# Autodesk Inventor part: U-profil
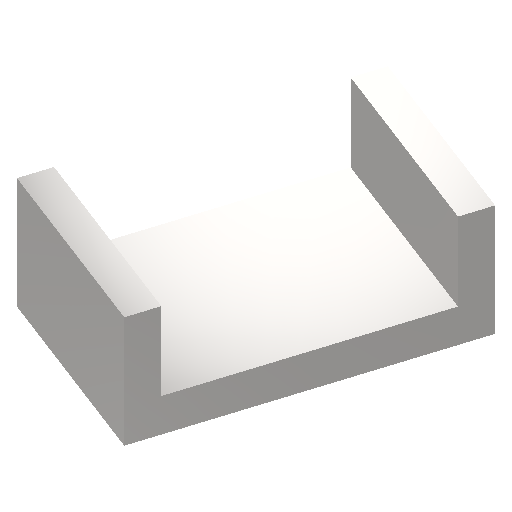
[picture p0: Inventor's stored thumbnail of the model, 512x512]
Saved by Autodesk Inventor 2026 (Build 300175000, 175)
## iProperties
Created: 2004-09
Part Number: U-profil
Document SubType Name: Modeling
Designer: Lars Bertram Pedersen
Manufacturer: Standard
Standards Organization: Custom
Material: Steel, Mild
Density: 7.85 g/cm^3
Appearance: Semi-Polished
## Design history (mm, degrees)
sketch "Sketch1"
  geometry: L1 (-44.965, 15.773)-(5.035, 15.773); L2 (5.035, 15.773)-(5.035, 35.773); L3 (5.035, 35.773)-(0.035, 35.773); L4 (0.035, 35.773)-(0.035, 21.773); L5 (0.035, 21.773)-(-39.965, 21.773); L6 (-39.965, 21.773)-(-39.965, 35.773); L7 (-39.965, 35.773)-(-44.965, 35.773); L8 (-44.965, 35.773)-(-44.965, 15.773)
  constraints: 16 end point, 5 perpendicular, 2 parallel, 1 horizontal
  dimensions: "d1" = 5 distance between parallel lines of L2 L4; "d3" = 50 distance of L1.start L1.end; "d4" = 14 distance between parallel lines of L3 L5; "d6" = 6 distance between parallel lines of L1 L5; "d7" = 5 distance of L6.end L7.end; "d8" = 20 distance of L7.end L1.start
extrude "Extrusion1" new body sketch "Sketch1" distance "d9" = 30; taper "d10" = 0 deg
body "Solid1"
